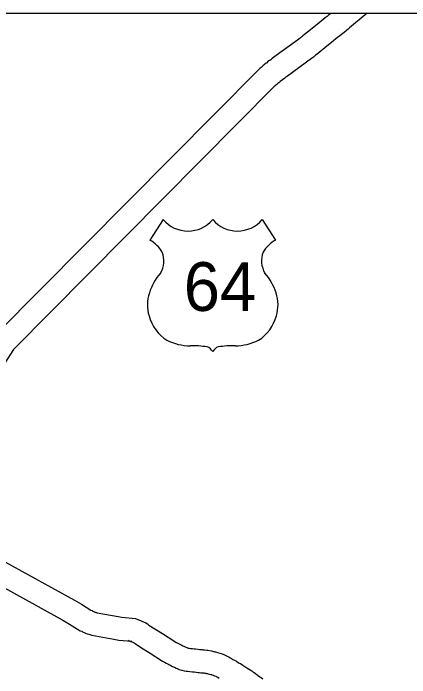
# Model space of a CAD drawing. Extents: x 1370567 to 1373900, y 377514 to 379648.
# Drawn here: x 1370802.8 to 1370854.4, y 379466.1 to 379552.5 of the extents above; entities that cross this region are included whole.
import ezdxf

# ---------------------------------------------------------------- set-up
doc = ezdxf.new("R2010")
doc.units = 0
doc.layers.add('Default', color=7, linetype='Continuous')
doc.layers.add('Survey Symbols', color=7, linetype='Continuous')

msp = doc.modelspace()

# ---------------------------------------------------------------- linework, layer by layer
at = {"layer": 'Default'}
for p, q in [((1370822.281, 379525.72), (1370820.55, 379523.043)), ((1370835.15, 379525.72), (1370836.881, 379523.043))]:
    msp.add_line(p, q, dxfattribs=at)
for points in [[(1370844.138, 379552.541), (1370844.028, 379552.457), (1370843.809, 379552.297), (1370843.603, 379552.131), (1370843.361, 379551.944), (1370843.109, 379551.746), (1370842.844, 379551.516), (1370842.569, 379551.301), (1370841.433, 379550.39), (1370840.667, 379549.763), (1370840.454, 379549.591), (1370840.263, 379549.447), (1370840.123, 379549.333), (1370839.934, 379549.17), (1370839.767, 379549.039), (1370836.689, 379546.814), (1370836.394, 379546.605), (1370836.284, 379546.506), (1370836.244, 379546.475), (1370836.177, 379546.422), (1370836.122, 379546.383), (1370835.907, 379546.252), (1370835.768, 379546.111), (1370835.673, 379546.05), (1370835.467, 379545.878), (1370835.401, 379545.819), (1370835.293, 379545.736), (1370835.199, 379545.654), (1370835.08, 379545.555), (1370835.022, 379545.503), (1370834.877, 379545.395), (1370834.689, 379545.204), (1370800.641, 379510.944)], [(1370848.805, 379552.541), (1370846.525, 379550.639), (1370846.35, 379550.487), (1370846.141, 379550.298), (1370845.829, 379550.057), (1370845.632, 379549.913), (1370845.461, 379549.776), (1370845.206, 379549.579), (1370845.021, 379549.433), (1370844.751, 379549.199), (1370844.43, 379548.948), (1370843.323, 379548.06), (1370842.56, 379547.435), (1370842.297, 379547.223), (1370842.111, 379547.083), (1370842.052, 379547.035), (1370841.844, 379546.855), (1370841.574, 379546.643), (1370838.435, 379544.375), (1370838.274, 379544.26), (1370838.205, 379544.198), (1370838.086, 379544.107), (1370837.791, 379543.874), (1370837.49, 379543.65), (1370837.446, 379543.622), (1370837.434, 379543.612), (1370837.321, 379543.51), (1370837.191, 379543.411), (1370837.146, 379543.371), (1370837.047, 379543.289), (1370836.926, 379543.18), (1370836.852, 379543.125), (1370836.823, 379543.095), (1370802.769, 379508.829)], [(1370802.769, 379508.829), (1370801.514, 379506.857)], [(1370801.765, 379481.144), (1370810.716, 379476.215), (1370811.628, 379475.674), (1370812.869, 379474.914), (1370813.01, 379474.854), (1370813.134, 379474.783), (1370813.295, 379474.713), (1370813.321, 379474.698), (1370813.42, 379474.662), (1370813.514, 379474.631), (1370813.609, 379474.601), (1370813.682, 379474.58), (1370816.398, 379474.085), (1370816.905, 379473.992), (1370818.673, 379473.847)], [(1370800.332, 379478.508), (1370809.227, 379473.61), (1370810.08, 379473.104), (1370811.487, 379472.243), (1370811.667, 379472.166), (1370811.783, 379472.099), (1370811.984, 379472.012), (1370812.178, 379471.907), (1370812.38, 379471.848), (1370812.439, 379471.826), (1370812.586, 379471.779), (1370812.731, 379471.731), (1370812.998, 379471.655), (1370815.861, 379471.133), (1370816.513, 379471.014), (1370818.177, 379470.878)], [(1370818.673, 379473.847), (1370819.184, 379473.622), (1370819.321, 379473.569), (1370819.498, 379473.496), (1370819.997, 379473.271), (1370820.232, 379473.134), (1370820.386, 379472.983), (1370822.2, 379471.871), (1370823.774, 379470.837), (1370823.969, 379470.724), (1370824.022, 379470.692), (1370824.105, 379470.657), (1370824.344, 379470.547), (1370824.538, 379470.441), (1370824.702, 379470.356), (1370824.829, 379470.282), (1370824.959, 379470.225), (1370825.207, 379470.115), (1370825.342, 379470.054), (1370825.417, 379470.02), (1370825.48, 379470), (1370825.524, 379469.99), (1370825.657, 379469.971), (1370825.842, 379469.947), (1370826.106, 379469.919), (1370826.29, 379469.894), (1370826.481, 379469.896), (1370826.821, 379469.848), (1370827.013, 379469.814), (1370827.104, 379469.804), (1370827.351, 379469.783), (1370827.488, 379469.76), (1370827.663, 379469.753), (1370827.95, 379469.715), (1370828.091, 379469.695), (1370828.297, 379469.665), (1370828.552, 379469.622), (1370828.808, 379469.554), (1370828.859, 379469.54), (1370828.985, 379469.51), (1370829.142, 379469.475), (1370829.351, 379469.429), (1370829.638, 379469.331), (1370829.807, 379469.263), (1370830.018, 379469.192), (1370830.148, 379469.138), (1370830.332, 379469.078), (1370830.511, 379468.984), (1370830.611, 379468.944), (1370830.822, 379468.841), (1370831.011, 379468.717), (1370831.095, 379468.658), (1370831.146, 379468.623), (1370831.209, 379468.587), (1370831.339, 379468.508), (1370831.534, 379468.394), (1370831.796, 379468.266), (1370832.088, 379468.083), (1370832.33, 379467.959), (1370832.647, 379467.766), (1370832.917, 379467.586), (1370833.044, 379467.503), (1370833.276, 379467.345), (1370833.397, 379467.266), (1370833.579, 379467.166), (1370833.806, 379467.007), (1370833.941, 379466.906), (1370834.096, 379466.812), (1370834.281, 379466.675), (1370834.507, 379466.502), (1370834.609, 379466.401), (1370834.812, 379466.285), (1370834.898, 379466.215), (1370835.029, 379466.147), (1370835.248, 379465.982)], [(1370817.696, 379471), (1370818.037, 379470.85), (1370818.201, 379470.786), (1370818.305, 379470.743), (1370818.49, 379470.66), (1370818.615, 379470.578), (1370819.341, 379470.104), (1370820.592, 379469.337), (1370822.199, 379468.282), (1370822.445, 379468.14), (1370822.654, 379468.014), (1370822.892, 379467.913), (1370822.995, 379467.866), (1370823.122, 379467.796), (1370823.26, 379467.724), (1370823.475, 379467.6), (1370823.746, 379467.482), (1370823.98, 379467.377), (1370824.106, 379467.32), (1370824.332, 379467.218), (1370824.69, 379467.102), (1370824.987, 379467.036), (1370825.254, 379466.998), (1370825.489, 379466.967), (1370825.745, 379466.941), (1370826.101, 379466.892), (1370826.289, 379466.894), (1370826.349, 379466.885), (1370826.577, 379466.844), (1370826.807, 379466.818), (1370826.979, 379466.803), (1370827.183, 379466.77), (1370827.407, 379466.761), (1370827.541, 379466.743), (1370827.66, 379466.726), (1370827.833, 379466.701), (1370827.919, 379466.687), (1370828.024, 379466.659), (1370828.113, 379466.634), (1370828.307, 379466.588), (1370828.491, 379466.546), (1370828.541, 379466.535), (1370828.595, 379466.517), (1370828.768, 379466.448), (1370828.958, 379466.383), (1370829.109, 379466.32), (1370829.165, 379466.302), (1370829.247, 379466.259), (1370829.351, 379466.217), (1370829.387, 379466.192), (1370829.537, 379466.089)]]:
    msp.add_lwpolyline(points, dxfattribs=at)
for centre, radius, start, end in [((1370825.504, 379528.432), 4.212, 220.07504, 319.67012), ((1370831.927, 379528.432), 4.212, 220.32988, 319.92496), ((1370818.288, 379519.157), 4.497, 30.7809, 59.98827), ((1370839.142, 379519.157), 4.497, 120.01173, 149.2191), ((1370819.278, 379520.343), 3.083, 328.81046, 21.21077), ((1370838.153, 379520.343), 3.083, 158.78923, 211.18954), ((1370827.339, 379514.025), 7.192, 138.95648, 162.69135), ((1370830.092, 379514.025), 7.192, 17.30865, 41.04352), ((1370824.965, 379514.614), 4.752, 160.95764, 197.38186), ((1370832.466, 379514.614), 4.752, 342.61814, 19.04236), ((1370825.738, 379514.627), 5.499, 195.10743, 237.13119), ((1370831.692, 379514.627), 5.499, 302.86881, 344.89257), ((1370825.841, 379516.359), 7.06, 244.07708, 269.57785), ((1370831.59, 379516.359), 7.06, 270.42215, 295.92292), ((1370826.004, 379496.368), 12.933, 81.19416, 90.95387), ((1370827.621, 379507.963), 1.239, 28.03422, 72.98637), ((1370829.809, 379507.963), 1.239, 107.01363, 151.96578), ((1370831.426, 379496.368), 12.933, 89.04613, 98.80584)]:
    msp.add_arc(centre, radius, start, end, dxfattribs=at)
at = {"layer": 'Survey Symbols'}
msp.add_lwpolyline([(1370727.274, 379552.541), (1371456.671, 379552.541), (1371456.671, 378768.055), (1370727.274, 378768.055)], close=True, dxfattribs=at)
msp.add_lwpolyline([(1370727.274, 379552.541), (1371456.671, 379552.541), (1371456.671, 378768.055), (1370727.274, 378768.055)], close=True, dxfattribs=at)
msp.add_lwpolyline([(1370727.274, 379552.541), (1371456.671, 379552.541), (1371456.671, 378768.055), (1370727.274, 378768.055)], close=True, dxfattribs=at)
msp.add_lwpolyline([(1370727.274, 379552.541), (1371456.671, 379552.541), (1371456.671, 378768.055), (1370727.274, 378768.055)], close=True, dxfattribs=at)
msp.add_lwpolyline([(1370727.274, 379552.541), (1371456.671, 379552.541), (1371456.671, 378768.055), (1370727.274, 378768.055)], close=True, dxfattribs=at)
msp.add_lwpolyline([(1370727.274, 379552.541), (1371456.671, 379552.541), (1371456.671, 378768.055), (1370727.274, 378768.055)], close=True, dxfattribs=at)

# ---------------------------------------------------------------- texts
at = {"layer": 'Default'}
msp.add_text('64', height=6.336, dxfattribs=at).set_placement((1370824.947, 379513.837))

doc.saveas('drawing.dxf')
